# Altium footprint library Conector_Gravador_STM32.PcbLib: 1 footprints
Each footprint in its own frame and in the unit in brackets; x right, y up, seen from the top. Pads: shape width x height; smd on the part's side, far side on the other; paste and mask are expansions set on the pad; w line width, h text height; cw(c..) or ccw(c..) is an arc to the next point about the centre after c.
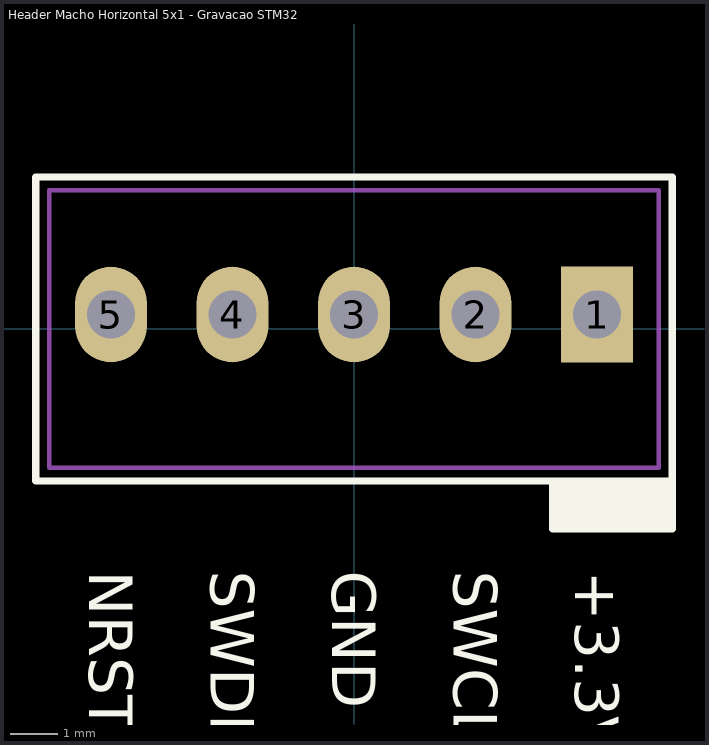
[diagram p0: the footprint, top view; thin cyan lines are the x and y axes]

## Header Macho Horizontal 5x1 - Gravacao STM32 [mm] "Header Macho Horizontal 5x1 - Gravacao STM32"
pads (5):
  rect 1.5x2 hole 1: 1(5.08,0.3)
  oval 1.5x2 hole 1: 2(2.54,0.3) 3(0,0.3) 4(-2.54,0.3) 5(-5.08,0.3)
Top Overlay:
  rectangle: 4.15,-4.175 6.65,-3.175
  lines w0.15: 4.15,-3.175 4.15,-4.175 5.65,-4.175 6.65,-4.175 6.65,-3.175 ; 6.65,-3.175 -6.65,-3.175 -6.65,3.175 6.65,3.175 6.65,-3.175
  text "+3.3V" at 4.623,-5.059 h0.91
  text "SWCLK" at 2.083,-5.059 h0.91
  text "SWDIO" at -2.997,-5.059 h0.91
  text "NRST" at -5.537,-5.059 h0.91
  text "GND" at -0.457,-5.059 h0.91
Mechanical 13:
  lines w0.1: -6.37,-2.9 -6.37,2.9 6.37,2.9 6.37,-2.9 -6.37,-2.9
Mechanical 15:
  lines w0.05: -0.5,0 0.5,0 ; 0,-0.5 0,0.5
3D body "61900511121.stp": height 11.53, standoff -3.37, extent -6.35,-2.9 6.35,2.9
